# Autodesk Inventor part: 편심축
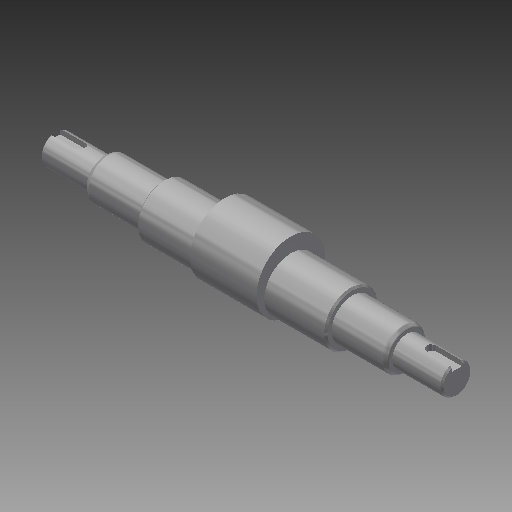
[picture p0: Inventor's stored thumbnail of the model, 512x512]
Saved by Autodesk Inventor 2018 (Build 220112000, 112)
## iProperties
Created: 2015-10
Part Number: 편심축
Document SubType Name: Modeling
Designer: mdu
Density: 1 g/cm^3
Material: 강철, 연강
Mass: 168.947 g
Surface Area: 248.524 cm^2
Volume: 168.947 cm^3
Appearance: 강철
Author: mdu
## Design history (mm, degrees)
sketch "스케치1"
  geometry: L1 (-20.5, -41.331)-(-20.5, 32.669) reference; L2 (7.5, -30.031)-(7.5, 21.369) reference; L3 (135.5, -30.331)-(135.5, 21.669) reference; L4 (121.5, 21.369)-(121.5, -30.031) reference; L5 (184.5, -4.331)-(-57.5, -4.331); L6 (184.5, -4.331)-(184.5, 4.669); L7 (154.5, 8.169)-(121.5, 8.169); L8 (121.5, 8.169)-(121.5, 11.669); L9 (121.5, 11.669)-(7.5, 11.669); L10 (7.5, 11.669)-(7.5, 8.169); L11 (7.5, 8.169)-(-27.5, 8.169); L12 (-27.5, 8.169)-(-27.5, 4.669); L13 (-27.5, 4.669)-(-57.5, 4.669); L14 (-57.5, 4.669)-(-57.5, -4.331); L15 (154.5, 8.169)-(154.5, 4.669); L16 (154.5, 4.669)-(184.5, 4.669); C1 r 32.5 at (64.5, -4.331) reference; 1 further point
  constraints: 24 end point, 8 perpendicular, 5 point on line, 3 parallel, 2 collinear
  dimensions: "d1" = 25 diameter of L11 L5; "d2" = 32 diameter of L9 L5; "d3" = 18 diameter of L13 L5; "d4" = 35 distance of L10.end L11.end; "d5" = 30 distance of L12.end L13.end; "d15" = 33 distance of L7.start L7.end; "d26" = 30 distance of L15.end L6.end
revolve "회전1" sketch "스케치1" stored, may be unused: angle "d6" = 90 deg
node "작업 평면1"
sketch "스케치2"
  geometry: C1 r 16 at (0, 0) reference; C2 r 20.75 at (0, 4)
  constraints: 1 centre point, 1 vertical alignment
  dimensions: "d34" = 4 distance of C2.centre C1.centre; "d35" = 41.5 diameter of C2
extrude "돌출1" join sketch "스케치2" stored distance "d9" = 40; taper "d10" = 0 deg
chamfer "모따기1" distance "d11" = 1; stored, may be unused: second distance "d12" = 2, angle "d13" = 45 deg
node "작업 평면2"
sketch "스케치3"
  geometry: L1 (-15, -8)-(-15, 8) reference; L2 (-15, 3)-(0, 3); L3 (0, -3)-(-15, -3); A1 r 3 centre (0, 0) between (0, -3) and (0, 3); 2 further points
  constraints: 4 end point, 2 perpendicular, 2 point on circle, 2 point on line, 2 tangent, 1 centre point, 1 horizontal alignment, 1 midpoint
  dimensions: "d16" = 18 dimension on A1 L1; "d17" = 6 distance between parallel lines of L3 L2
extrude "돌출2" cut sketch "스케치3" distance "d18" = 3.5; taper "d19" = 0 deg
node "작업 평면3"
chamfer "모따기2" distance "d36" = 2.2; stored, may be unused: second distance "d37" = 2, angle "d38" = 30 deg
chamfer "모따기3" distance "d39" = 2.2; stored, may be unused: second distance "d40" = 2, angle "d41" = 30 deg
fillet "모깎기1" dims "d42" = 1, "d43" = 2
fillet "모깎기2" dims "d44" = 1, "d45" = 2
node "솔리드1"
mirror "대칭1"
node "참조1"
node "참조2"
node "참조3"
node "참조4"
node "참조5"
other parameters: "d30" = 35
